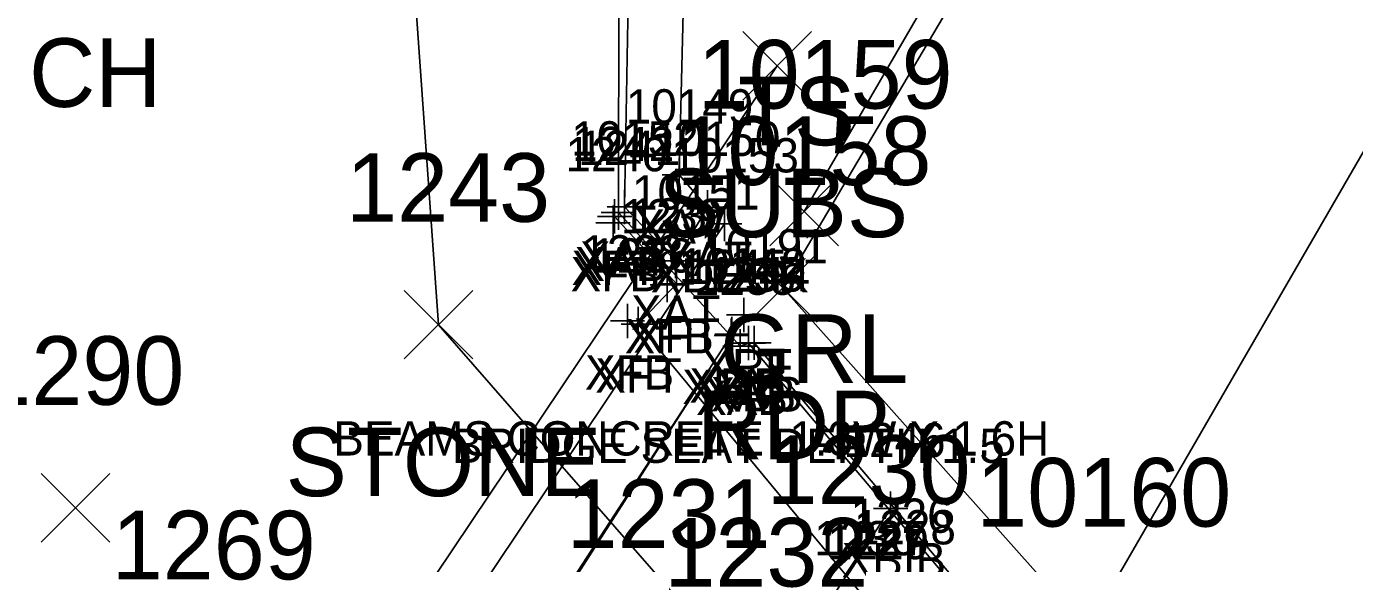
# Model space of a CAD drawing. Extents: x 1651685 to 1653558, y 889533 to 891085.
# Drawn here: x 1652681.1 to 1652719.83, y 890276.18 to 890291.84 of the extents above; entities that cross this region are included whole.
import ezdxf

# ---------------------------------------------------------------- set-up
doc = ezdxf.new("R2010")
doc.units = 0
for name, color, linetype in [('B_A', 7, 'Continuous'), ('B_C', 7, 'Continuous'), ('B_I', 7, 'Continuous'), ('B_TIC', 7, 'Continuous'), ('BB', 7, 'Continuous'), ('BELB', 7, 'Continuous'), ('BFT', 7, 'Continuous'), ('BR', 7, 'Continuous'), ('BSE', 7, 'Continuous'), ('BSUBM', 7, 'Continuous'), ('L_A', 7, 'Continuous'), ('L_I', 7, 'Continuous'), ('L_TIC', 7, 'Continuous'), ('LASF', 7, 'Continuous'), ('P_A', 7, 'Continuous'), ('P_I', 7, 'Continuous'), ('P_TIC', 7, 'Continuous'), ('PET', 7, 'Continuous'), ('PRC', 7, 'Continuous'), ('R_A', 7, 'Continuous'), ('R_I', 7, 'Continuous'), ('R_TIC', 7, 'Continuous'), ('RGR', 7, 'Continuous'), ('U_A', 7, 'Continuous'), ('U_TIC', 7, 'Continuous'), ('USA', 7, 'Continuous')]:
    doc.layers.add(name, color=color, linetype=linetype)

msp = doc.modelspace()

# ---------------------------------------------------------------- linework, layer by layer
at = {"layer": 'B_TIC'}
for p, q in [((1652700.14, 890287.511), (1652700.216, 890287.511)), ((1652700.14, 890287.511), (1652700.216, 890287.511)), ((1652698.256, 890286.301), (1652698.332, 890286.301)), ((1652698.367, 890286.414), (1652698.443, 890286.414)), ((1652698.541, 890286.578), (1652698.617, 890286.578)), ((1652700.969, 890286.566), (1652701.045, 890286.566)), ((1652698.214, 890286.117), (1652698.289, 890286.117)), ((1652701.466, 890286.084), (1652701.541, 890286.084)), ((1652700.033, 890285.003), (1652700.108, 890285.003)), ((1652699.791, 890284.306), (1652699.867, 890284.306)), ((1652700.065, 890284.332), (1652700.141, 890284.332)), ((1652698.634, 890283.254), (1652698.709, 890283.254)), ((1652702.025, 890283.431), (1652702.101, 890283.431)), ((1652698.949, 890283.164), (1652699.025, 890283.164)), ((1652701.661, 890282.829), (1652701.736, 890282.829)), ((1652701.679, 890282.871), (1652701.755, 890282.871)), ((1652701.915, 890282.515), (1652701.991, 890282.515)), ((1652702.159, 890282.607), (1652702.234, 890282.607)), ((1652702.325, 890282.616), (1652702.401, 890282.616)), ((1652706.309, 890277.782), (1652706.385, 890277.782))]:
    msp.add_line(p, q, dxfattribs=at)
for points in [[(1652700.137, 890287.011), (1652700.137, 890288.011)], [(1652700.137, 890287.011), (1652700.137, 890288.011)], [(1652699.637, 890287.511), (1652700.637, 890287.511)], [(1652699.637, 890287.511), (1652700.637, 890287.511)], [(1652698.538, 890286.078), (1652698.538, 890287.078)], [(1652700.966, 890286.066), (1652700.966, 890287.066)], [(1652698.253, 890285.801), (1652698.253, 890286.801)], [(1652698.364, 890285.914), (1652698.364, 890286.914)], [(1652697.753, 890286.301), (1652698.753, 890286.301)], [(1652697.864, 890286.414), (1652698.864, 890286.414)], [(1652698.038, 890286.578), (1652699.038, 890286.578)], [(1652698.21, 890285.617), (1652698.21, 890286.617)], [(1652700.466, 890286.566), (1652701.466, 890286.566)], [(1652701.462, 890285.584), (1652701.462, 890286.584)], [(1652697.71, 890286.117), (1652698.71, 890286.117)], [(1652700.962, 890286.084), (1652701.962, 890286.084)], [(1652700.029, 890284.503), (1652700.029, 890285.503)], [(1652699.529, 890285.003), (1652700.529, 890285.003)], [(1652699.788, 890283.806), (1652699.788, 890284.806)], [(1652700.062, 890283.832), (1652700.062, 890284.832)], [(1652699.288, 890284.306), (1652700.288, 890284.306)], [(1652699.562, 890284.332), (1652700.562, 890284.332)], [(1652698.63, 890282.754), (1652698.63, 890283.754)], [(1652698.946, 890282.664), (1652698.946, 890283.664)], [(1652702.022, 890282.931), (1652702.022, 890283.931)], [(1652698.13, 890283.254), (1652699.13, 890283.254)], [(1652701.522, 890283.431), (1652702.522, 890283.431)], [(1652701.657, 890282.329), (1652701.657, 890283.329)], [(1652701.676, 890282.371), (1652701.676, 890283.371)], [(1652698.446, 890283.164), (1652699.446, 890283.164)], [(1652701.157, 890282.829), (1652702.157, 890282.829)], [(1652701.176, 890282.871), (1652702.176, 890282.871)], [(1652701.912, 890282.015), (1652701.912, 890283.015)], [(1652702.155, 890282.107), (1652702.155, 890283.107)], [(1652702.322, 890282.116), (1652702.322, 890283.116)], [(1652701.412, 890282.515), (1652702.412, 890282.515)], [(1652701.655, 890282.607), (1652702.655, 890282.607)], [(1652701.822, 890282.616), (1652702.822, 890282.616)], [(1652706.306, 890277.282), (1652706.306, 890278.282)], [(1652705.806, 890277.782), (1652706.806, 890277.782)]]:
    msp.add_lwpolyline(points, dxfattribs=at)
at = {"layer": 'BB'}
for points in [[(1652701.657, 890282.829), (1652688.903, 890263.246)], [(1652706.306, 890277.782), (1652693.372, 890258.116)]]:
    msp.add_lwpolyline(points, dxfattribs=at)
at = {"layer": 'BELB'}
msp.add_lwpolyline([(1652686.272, 890263.4), (1652701.462, 890286.084)], dxfattribs=at)
at = {"layer": 'BFT'}
msp.add_lwpolyline([(1652714.411, 890266.114), (1652706.512, 890275.575), (1652705.765, 890274.921), (1652698.946, 890283.164), (1652700.062, 890284.332), (1652698.253, 890286.301)], dxfattribs=at)
at = {"layer": 'BR'}
msp.add_lwpolyline([(1652688.519, 890262.387), (1652701.676, 890282.871), (1652702.022, 890283.431)], dxfattribs=at)
at = {"layer": 'BSE'}
msp.add_lwpolyline([(1652702.322, 890282.616), (1652723.867, 890257.21)], dxfattribs=at)
at = {"layer": 'BSUBM'}
for points in [[(1652730.91, 890251.239), (1652729.609, 890250.415), (1652721.751, 890259.535), (1652713.874, 890268.743), (1652713.817, 890268.822), (1652702.155, 890282.607), (1652701.912, 890282.515), (1652698.364, 890286.414), (1652698.385, 890299.877), (1652698.504, 890301.956), (1652700.485, 890302.125)], [(1652700.137, 890287.511), (1652700.966, 890286.566), (1652700.029, 890285.003), (1652698.538, 890286.578), (1652698.815, 890301.832), (1652700.483, 890301.714)], [(1652700.137, 890287.511), (1652700.483, 890301.714)]]:
    msp.add_lwpolyline(points, dxfattribs=at)
at = {"layer": 'L_TIC'}
for points in [[(1652692.116, 890282.145), (1652694.116, 890284.145)], [(1652694.116, 890282.145), (1652692.116, 890284.145)], [(1652681.531, 890276.807), (1652683.531, 890278.807)], [(1652683.531, 890276.807), (1652681.531, 890278.807)]]:
    msp.add_lwpolyline(points, dxfattribs=at)
at = {"layer": 'LASF'}
msp.add_lwpolyline([(1652702.399, 890272.508), (1652693.116, 890283.145), (1652692.048, 890298.23), (1652676.075, 890310.97), (1652670.462, 890321.805), (1652673.396, 890326.853)], dxfattribs=at)
at = {"layer": 'P_TIC'}
for points in [[(1652702.162, 890283.218), (1652704.162, 890285.218)], [(1652704.162, 890283.218), (1652702.162, 890285.218)], [(1652702.162, 890283.218), (1652704.162, 890285.218)], [(1652704.162, 890283.218), (1652702.162, 890285.218)]]:
    msp.add_lwpolyline(points, dxfattribs=at)
at = {"layer": 'PET'}
for points in [[(1652703.162, 890284.218), (1652712.816, 890300.527), (1652728.548, 890330.545), (1652742.129, 890361.562), (1652749.201, 890378.01), (1652759.762, 890406.833), (1652771.728, 890443.525), (1652776.682, 890458.628), (1652791.905, 890507.528)], [(1652703.162, 890284.218), (1652712.038, 890274.257), (1652722.331, 890261.916), (1652735.137, 890284.012), (1652751.621, 890318.115), (1652767.723, 890357.351), (1652783.179, 890400.145), (1652797.7, 890444.761), (1652815.977, 890499.358)]]:
    msp.add_lwpolyline(points, dxfattribs=at)
at = {"layer": 'PRC'}
msp.add_lwpolyline([(1652712.038, 890274.257), (1652722.864, 890292.979), (1652739.686, 890324.96), (1652756.287, 890362.602), (1652772.674, 890406.812), (1652786.214, 890448.938), (1652804.537, 890503.78)], dxfattribs=at)
at = {"layer": 'R_TIC'}
for points in [[(1652702.785, 890285.446), (1652704.785, 890287.446)], [(1652704.785, 890285.446), (1652702.785, 890287.446)]]:
    msp.add_lwpolyline(points, dxfattribs=at)
at = {"layer": 'RGR'}
msp.add_lwpolyline([(1652703.785, 890286.446), (1652712.293, 890301.085), (1652727.675, 890331.014), (1652743.089, 890366.713), (1652744.455, 890374.508), (1652743.705, 890381.112)], dxfattribs=at)
at = {"layer": 'U_TIC'}
for points in [[(1652701.995, 890289.696), (1652703.995, 890291.696)], [(1652703.995, 890289.696), (1652701.995, 890291.696)]]:
    msp.add_lwpolyline(points, dxfattribs=at)
at = {"layer": 'USA'}
msp.add_lwpolyline([(1652683.047, 890260.957), (1652702.995, 890290.696)], dxfattribs=at)

# ---------------------------------------------------------------- texts
at = {"layer": 'B_A'}
for s, p in [('XAT', (1652698.842, 890285.511)), ('XAT', (1652698.842, 890285.511)), ('XAT', (1652697.243, 890284.578)), ('XAT', (1652699.67, 890284.566)), ('XFT', (1652696.997, 890284.301)), ('XAB', (1652697.084, 890284.414)), ('XFB', (1652696.97, 890284.117)), ('XDECK', (1652699.305, 890284.084)), ('XAT', (1652698.734, 890283.003)), ('XFB', (1652698.548, 890282.306)), ('XFT', (1652698.806, 890282.332)), ('XRF', (1652700.782, 890281.431)), ('XFB', (1652697.39, 890281.254)), ('XFT', (1652697.69, 890281.164)), ('XBIB', (1652700.228, 890280.829)), ('XRF', (1652700.436, 890280.871)), ('XAB', (1652700.632, 890280.515)), ('XAB', (1652700.876, 890280.607)), ('XBS', (1652701.062, 890280.616)), ('XBIB', (1652704.877, 890275.782))]:
    msp.add_text(s, height=1, dxfattribs=at).set_placement(p)
at = {"layer": 'B_C'}
for s, p in [('BEAMS CONCRETE  1.3W X 1.6H', (1652690.051, 890279.329)), ('BRIDGE SEAT DEPTH 1.5', (1652693.511, 890279.116))]:
    msp.add_text(s, height=1, dxfattribs=at).set_placement(p)
at = {"layer": 'B_I'}
for s, p in [('10149', (1652698.582, 890289.011)), ('10149', (1652698.582, 890289.011)), ('10152', (1652696.987, 890288.078)), ('10150', (1652699.371, 890288.066)), ('1240', (1652696.821, 890287.617)), ('1242', (1652697.018, 890287.914)), ('1241', (1652697.19, 890287.801)), ('10153', (1652699.911, 890287.584)), ('10151', (1652698.762, 890286.503)), ('1239', (1652698.438, 890285.806)), ('1237', (1652698.715, 890285.832)), ('10191', (1652700.754, 890284.931)), ('1238', (1652697.284, 890284.754)), ('1236', (1652697.572, 890284.664)), ('10148', (1652700.125, 890284.371)), ('1245', (1652700.311, 890284.329)), ('1233', (1652700.809, 890284.107)), ('1244', (1652700.975, 890284.116)), ('1235', (1652700.565, 890284.015)), ('1246', (1652704.932, 890279.282)), ('1226', (1652705.138, 890277.075)), ('1230', (1652704.076, 890276.419)), ('1227', (1652704.419, 890276.421)), ('1228', (1652705.235, 890276.738)), ('1229', (1652704.452, 890276.305))]:
    msp.add_text(s, height=1, dxfattribs=at).set_placement(p)
at = {"layer": 'L_A'}
for s, p in [('CH', (1652681.175, 890289.495)), ('TS', (1652701.85, 890288.375)), ('STONE', (1652688.659, 890278.145))]:
    msp.add_text(s, height=2, dxfattribs=at).set_placement(p)
at = {"layer": 'L_I'}
for s, p in [('1243', (1652690.423, 890286.145)), ('1290', (1652679.752, 890280.807)), ('1230', (1652702.687, 890277.919)), ('1231', (1652696.854, 890276.636)), ('1269', (1652683.587, 890275.718)), ('1232', (1652699.706, 890275.508))]:
    msp.add_text(s, height=2, dxfattribs=at).set_placement(p)
at = {"layer": 'P_A'}
msp.add_text('RDP', height=2, dxfattribs=at).set_placement((1652700.65, 890279.218))
msp.add_text('RDP', height=2, dxfattribs=at).set_placement((1652700.65, 890279.218))
at = {"layer": 'P_I'}
for s, p in [('10158', (1652700.06, 890287.218)), ('10158', (1652700.06, 890287.218)), ('10160', (1652708.802, 890277.257)), ('10160', (1652708.802, 890277.257))]:
    msp.add_text(s, height=2, dxfattribs=at).set_placement(p)
at = {"layer": 'R_A'}
msp.add_text('GRL', height=2, dxfattribs=at).set_placement((1652701.328, 890281.446))
at = {"layer": 'R_I'}
msp.add_text('10159', height=2, dxfattribs=at).set_placement((1652700.675, 890289.446))
at = {"layer": 'U_A'}
msp.add_text('SUBS', height=2, dxfattribs=at).set_placement((1652699.531, 890285.696))

doc.saveas('drawing.dxf')
